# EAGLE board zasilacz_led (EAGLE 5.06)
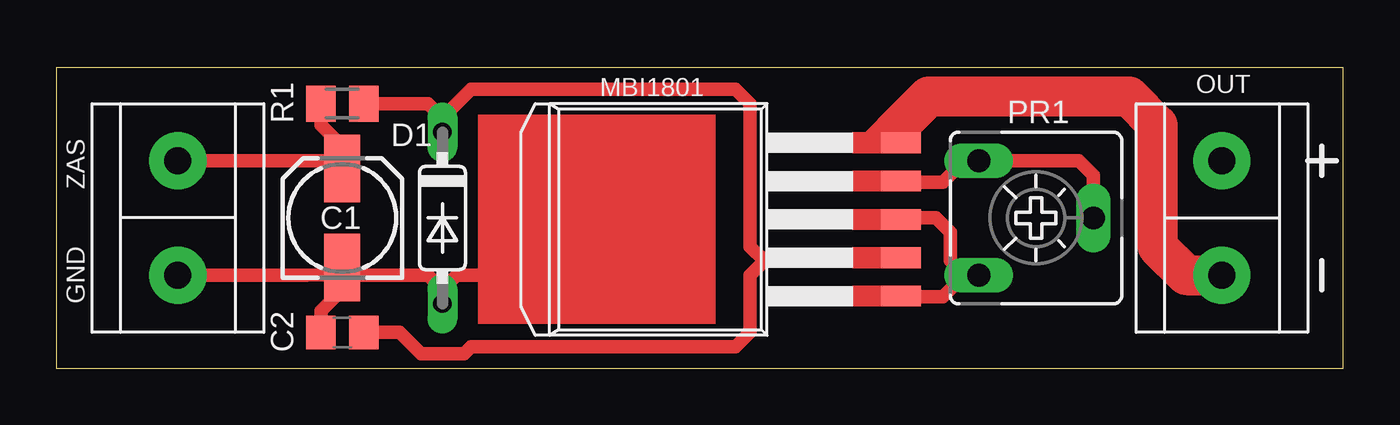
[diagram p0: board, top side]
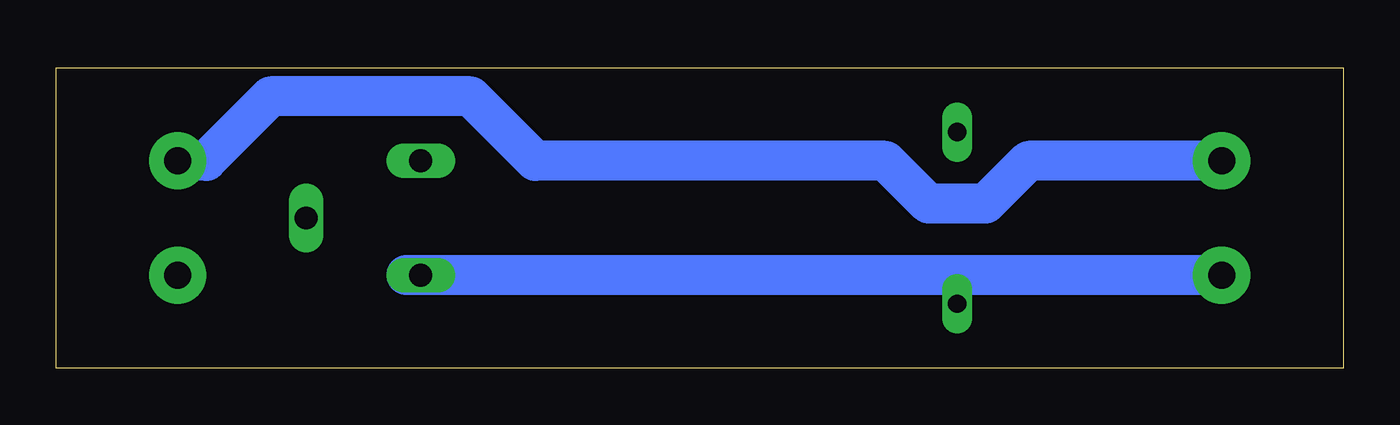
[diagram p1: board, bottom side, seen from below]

Size 57.14 x 13.32 mm. Coordinates in mm from the lower left corner, seen from the top.
Outline: 0,0 57.14,0 57.14,13.32 0,13.32 0,0
Copper layers (1*16): Top 0.035mm / dielectric 1.5mm / Bottom 0.035mm
Design rules "default": minimum track width 10mil, minimum drill 24mil, track to track 8mil, track to pad 8mil, pad to pad 8mil, via to via 8mil, smd to smd 8mil, copper to edge 40mil, drill to drill 8mil, minimum pad ring 10mil, minimum via ring 8mil, stop-mask expansion 4mil, vias tented up to drill 0mil, thermal gap 10mil

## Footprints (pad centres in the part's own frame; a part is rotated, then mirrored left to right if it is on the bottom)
153CLV-0505 = smd 3 x 1.6: + 2.2,0; - -2.2,0
C0805 = smd 1.3 x 1.5: 1 -0.95,0; 2 0.95,0
DO35-7 = drill 0.813 long: A 3.81,0; C -3.81,0
CA6V = drill 1.016 long: A -2.54,-2.54; E 2.54,-2.54; S 0,2.54
M0805 = smd 1.3 x 1.6: 1 -0.95,0; 2 0.95,0
MBI1801 = smd 0.914 x 1.778: P$1 -3.467,-10.516; P$2 -1.765,-10.516; P$3 -0.064,-10.516; P$4 1.638,-10.516; P$5 3.34,-10.516
ARK2 = drill 1.2 pad 2.54 round: P$3 -2.54,0; P$4 2.54,0

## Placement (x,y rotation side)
C1  22uF/25V  [153CLV-0505]  12.7,6.67 90 top
C2  100nF  [C0805]  12.7,1.59 180 top
D1  5,1V  [DO35-7]  17.15,6.67 270 top
PR1  50k  [CA6V]  43.5,6.67 270 top
R1  470  [M0805]  12.7,11.75 180 top
U1  MBI1801  [MBI1801]  26.99,6.67 90 top
U$2  ARK2  [ARK2]  5.4,6.67 90 top
U$3  ARK2  [ARK2]  51.75,6.67 270 top

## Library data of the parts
C1 C2 R1 = rcl
D1 = diode
PR1 = pot
U1 = mbi1801
U$2 U$3 = ark2_5mm

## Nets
GND: C1.- C2.2 D1.A PR1.E U1.P$1 U1.P$3 U$2.P$3
N$1: PR1.A PR1.S U1.P$4
N$2: C2.1 D1.C R1.1 U1.P$2
N$3: C1.+ R1.2 U$2.P$4 U$3.P$3
N$4: U1.P$5 U$3.P$4

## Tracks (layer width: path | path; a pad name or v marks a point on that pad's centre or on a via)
GND
  Top 0.406: U1.P$1 39.4,3.2 40.32,4.13 | U1.P$3 39.12,6.6 39.69,6.03
  Top 0.61: C1.- 12.72,4.15 11.11,4.13 U$2.P$3 | C1.- 13.02,4.45 12.7,4.13 | 40.32,4.13 39.37,3.17 37.47,3.17 | PR1.E 40.32,4.13 | 40.32,4.13 39.69,4.76 39.69,6.03 39.05,6.67 37.15,6.67 | C2.2 11.75,2.54 12.7,3.49 12.7,4.13 | C1.- 12.7,4.13 | 12.7,4.13 16.51,4.13 17.15,3.49 | D1.A 17.15,3.49 | 17.15,3.49 17.78,4.13 19.37,4.13
  Bottom 1.778: U$2.P$3 PR1.E 41.59,4.13
N$1
  Top 0.406: PR1.A 45.4,9.21 | U1.P$4 39.42,8.31 40.32,9.21
  Top 0.61: 40.64,9.21 PR1.A | 40.64,9.21 40.32,9.21 39.37,8.25 37.15,8.25 | PR1.S 46.04,8.57 45.4,9.21 40.64,9.21
N$2
  Top 0.61: U1.P$2 31.57,4.9 31.43,4.76 | 31.43,4.76 30.8,4.13 30.8,1.59 30.16,0.95 18.41,0.95 18.1,0.63 16.19,0.63 15.24,1.59 C2.1 | 31.43,4.76 30.8,5.4 30.8,11.75 30.16,12.38 18.41,12.38 17.15,11.11 | R1.1 15.24,11.74 16.51,11.74 17.15,11.11 | 17.15,11.11 D1.C
N$3
  Top 0.61: U$2.P$4 12.7,9.21 12.99,8.87 C1.+ 12.7,9.84 11.75,10.79 R1.2
  Bottom 1.778: U$2.P$4 13.97,9.21 15.87,7.3 18.41,7.3 20.32,9.21 35.88,9.21 38.74,12.06 47.63,12.06 50.48,9.21 U$3.P$3
N$4
  Top 0.406: 37.15,10.48 37.15,10.36 U1.P$5
  Top 1.778: U$3.P$4 50.16,4.13 48.9,5.4 48.9,10.8 47.63,12.06 38.74,12.06 37.15,10.48
N$5
  Top 0.406: 37.15,11.43 35.88,10.16 37.78,10.16

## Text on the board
tPlace: OUT | MBI1801 | ZAS | GND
